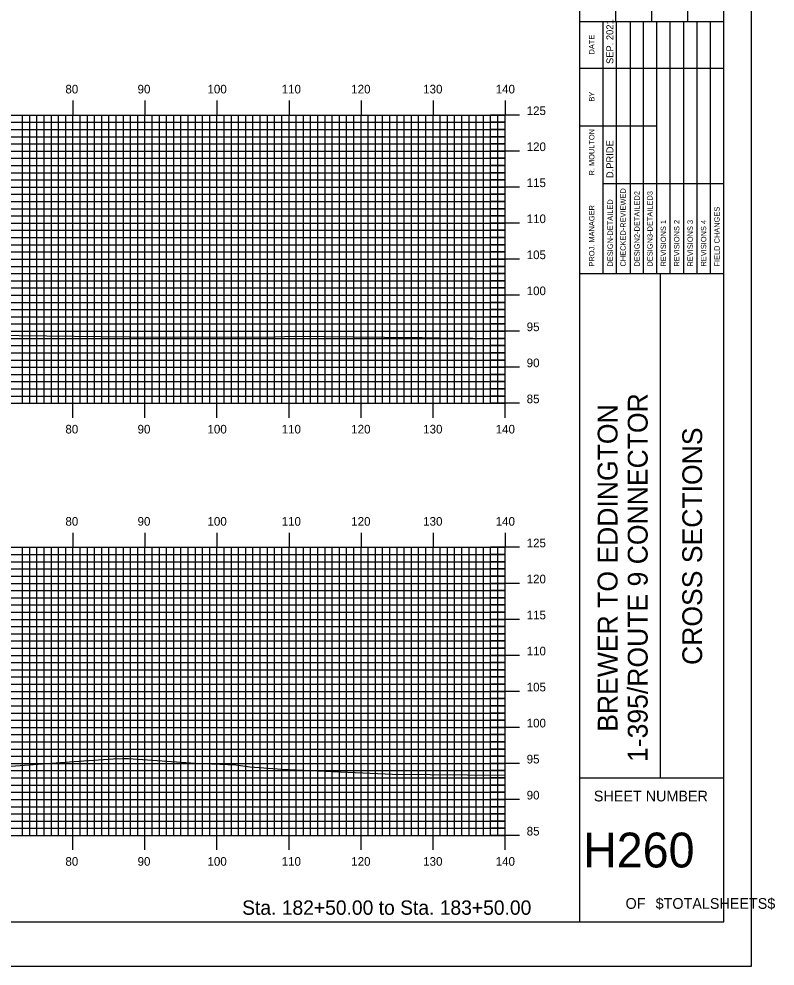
# Model space of a CAD drawing. Extents: x 1786582 to 1786926, y 442591 to 442811.
# Drawn here: x 1786820.6 to 1786925.6, y 442590.5 to 442722 of the extents above; entities that cross this region are included whole.
import ezdxf

# ---------------------------------------------------------------- set-up
doc = ezdxf.new("R2010")
doc.units = 0
for name, color, linetype in [('BORDER', 7, 'Continuous'), ('H_V ANNOTATION', 7, 'Continuous'), ('MAJOR', 7, 'Continuous'), ('MINOR', 7, 'Continuous'), ('PLOT BOUNDARY', 7, 'Continuous'), ('S_Roadway_Centerline', 7, 'Continuous')]:
    doc.layers.add(name, color=color, linetype=linetype)

msp = doc.modelspace()

# ---------------------------------------------------------------- linework, layer by layer
at = {"layer": 'BORDER'}
for p, q in [((1786898.48, 442596.67), (1786898.48, 442806.67)), ((1786903.48, 442721.67), (1786903.48, 442738.97)), ((1786908.48, 442721.67), (1786908.48, 442738.97)), ((1786913.48, 442721.67), (1786913.48, 442738.97)), ((1786898.48, 442721.67), (1786918.48, 442721.67)), ((1786898.48, 442686.67), (1786918.48, 442686.67)), ((1786909.66, 442616.67), (1786909.66, 442686.67)), ((1786898.48, 442616.67), (1786918.48, 442616.67))]:
    msp.add_line(p, q, dxfattribs=at)
msp.add_lwpolyline([(1786598.48, 442596.67), (1786918.48, 442596.67), (1786918.48, 442806.67), (1786598.48, 442806.67)], close=True, dxfattribs=at)
for points in [[(1786901.71, 442715.17), (1786901.71, 442721.67)], [(1786903.57, 442686.68), (1786903.57, 442721.67)], [(1786905.44, 442721.67), (1786905.44, 442686.68)], [(1786907.3, 442686.68), (1786907.3, 442721.67)], [(1786909.16, 442686.68), (1786909.16, 442721.67)], [(1786911.03, 442686.68), (1786911.03, 442721.67)], [(1786912.89, 442686.68), (1786912.89, 442721.67)], [(1786914.75, 442686.68), (1786914.75, 442721.67)], [(1786916.62, 442686.68), (1786916.62, 442721.67)], [(1786901.71, 442686.68), (1786901.71, 442720.26)], [(1786898.48, 442715.17), (1786918.48, 442715.17)], [(1786898.48, 442707.17), (1786901.71, 442707.17)], [(1786901.71, 442707.17), (1786909.16, 442707.17)], [(1786901.71, 442699.17), (1786918.48, 442699.17)]]:
    msp.add_lwpolyline(points, dxfattribs=at)
at = {"layer": 'MAJOR'}
for p, q in [((1786828.08, 442710.67), (1786828.08, 442708.67)), ((1786838.08, 442710.67), (1786838.08, 442708.67)), ((1786848.08, 442710.67), (1786848.08, 442708.67)), ((1786858.08, 442710.67), (1786858.08, 442708.67)), ((1786868.08, 442710.67), (1786868.08, 442708.67)), ((1786878.08, 442710.67), (1786878.08, 442708.67)), ((1786888.08, 442710.67), (1786888.08, 442708.67)), ((1786608.08, 442708.67), (1786888.08, 442708.67)), ((1786608.08, 442708.67), (1786888.08, 442708.67)), ((1786828.08, 442668.67), (1786828.08, 442708.67)), ((1786838.08, 442668.67), (1786838.08, 442708.67)), ((1786848.08, 442668.67), (1786848.08, 442708.67)), ((1786858.08, 442668.67), (1786858.08, 442708.67)), ((1786868.08, 442668.67), (1786868.08, 442708.67)), ((1786878.08, 442668.67), (1786878.08, 442708.67)), ((1786890.08, 442708.67), (1786886.07, 442708.67)), ((1786888.08, 442668.67), (1786888.08, 442708.67)), ((1786888.08, 442668.67), (1786888.08, 442708.67)), ((1786608.08, 442703.67), (1786888.08, 442703.67)), ((1786890.08, 442703.67), (1786886.07, 442703.67)), ((1786608.08, 442698.67), (1786888.08, 442698.67)), ((1786890.08, 442698.67), (1786886.07, 442698.67)), ((1786608.08, 442693.67), (1786888.08, 442693.67)), ((1786890.08, 442693.67), (1786886.07, 442693.67)), ((1786608.08, 442688.67), (1786888.08, 442688.67)), ((1786890.08, 442688.67), (1786886.07, 442688.67)), ((1786608.08, 442683.67), (1786888.08, 442683.67)), ((1786890.08, 442683.67), (1786886.07, 442683.67)), ((1786608.08, 442678.67), (1786888.08, 442678.67)), ((1786890.08, 442678.67), (1786886.07, 442678.67)), ((1786608.08, 442673.67), (1786888.08, 442673.67)), ((1786890.08, 442673.67), (1786886.07, 442673.67)), ((1786608.08, 442668.67), (1786888.08, 442668.67)), ((1786608.08, 442668.67), (1786888.08, 442668.67)), ((1786828.08, 442666.66), (1786828.08, 442668.67)), ((1786838.08, 442666.66), (1786838.08, 442668.67)), ((1786848.08, 442666.66), (1786848.08, 442668.67)), ((1786858.08, 442666.66), (1786858.08, 442668.67)), ((1786868.08, 442666.66), (1786868.08, 442668.67)), ((1786878.08, 442666.66), (1786878.08, 442668.67)), ((1786890.08, 442668.67), (1786886.07, 442668.67)), ((1786888.08, 442666.66), (1786888.08, 442668.67)), ((1786828.08, 442650.67), (1786828.08, 442648.67)), ((1786838.08, 442650.67), (1786838.08, 442648.67)), ((1786848.08, 442650.67), (1786848.08, 442648.67)), ((1786858.08, 442650.67), (1786858.08, 442648.67)), ((1786868.08, 442650.67), (1786868.08, 442648.67)), ((1786878.08, 442650.67), (1786878.08, 442648.67)), ((1786888.08, 442650.67), (1786888.08, 442648.67)), ((1786608.08, 442648.67), (1786888.08, 442648.67)), ((1786608.08, 442648.67), (1786888.08, 442648.67)), ((1786828.08, 442608.67), (1786828.08, 442648.67)), ((1786838.08, 442608.67), (1786838.08, 442648.67)), ((1786848.08, 442608.67), (1786848.08, 442648.67)), ((1786858.08, 442608.67), (1786858.08, 442648.67)), ((1786868.08, 442608.67), (1786868.08, 442648.67)), ((1786878.08, 442608.67), (1786878.08, 442648.67)), ((1786890.08, 442648.67), (1786886.07, 442648.67)), ((1786888.08, 442608.67), (1786888.08, 442648.67)), ((1786888.08, 442608.67), (1786888.08, 442648.67)), ((1786608.08, 442643.67), (1786888.08, 442643.67)), ((1786890.08, 442643.67), (1786886.07, 442643.67)), ((1786608.08, 442638.67), (1786888.08, 442638.67)), ((1786890.08, 442638.67), (1786886.07, 442638.67)), ((1786608.08, 442633.67), (1786888.08, 442633.67)), ((1786890.08, 442633.67), (1786886.07, 442633.67)), ((1786608.08, 442628.67), (1786888.08, 442628.67)), ((1786890.08, 442628.67), (1786886.07, 442628.67)), ((1786608.08, 442623.67), (1786888.08, 442623.67)), ((1786890.08, 442623.67), (1786886.07, 442623.67)), ((1786608.08, 442618.67), (1786888.08, 442618.67)), ((1786890.08, 442618.67), (1786886.07, 442618.67)), ((1786608.08, 442613.67), (1786888.08, 442613.67)), ((1786890.08, 442613.67), (1786886.07, 442613.67)), ((1786608.08, 442608.67), (1786888.08, 442608.67)), ((1786608.08, 442608.67), (1786888.08, 442608.67)), ((1786828.08, 442606.66), (1786828.08, 442608.67)), ((1786838.08, 442606.66), (1786838.08, 442608.67)), ((1786848.08, 442606.66), (1786848.08, 442608.67)), ((1786858.08, 442606.66), (1786858.08, 442608.67)), ((1786868.08, 442606.66), (1786868.08, 442608.67)), ((1786878.08, 442606.66), (1786878.08, 442608.67)), ((1786890.08, 442608.67), (1786886.07, 442608.67)), ((1786888.08, 442606.66), (1786888.08, 442608.67))]:
    msp.add_line(p, q, dxfattribs=at)
at = {"layer": 'MINOR'}
for p, q in [((1786821.08, 442668.67), (1786821.08, 442708.67)), ((1786822.08, 442668.67), (1786822.08, 442708.67)), ((1786823.08, 442668.67), (1786823.08, 442708.67)), ((1786824.08, 442668.67), (1786824.08, 442708.67)), ((1786825.08, 442668.67), (1786825.08, 442708.67)), ((1786826.08, 442668.67), (1786826.08, 442708.67)), ((1786827.08, 442668.67), (1786827.08, 442708.67)), ((1786829.08, 442668.67), (1786829.08, 442708.67)), ((1786830.08, 442668.67), (1786830.08, 442708.67)), ((1786831.08, 442668.67), (1786831.08, 442708.67)), ((1786832.08, 442668.67), (1786832.08, 442708.67)), ((1786833.08, 442668.67), (1786833.08, 442708.67)), ((1786834.08, 442668.67), (1786834.08, 442708.67)), ((1786835.08, 442668.67), (1786835.08, 442708.67)), ((1786836.08, 442668.67), (1786836.08, 442708.67)), ((1786837.08, 442668.67), (1786837.08, 442708.67)), ((1786839.08, 442668.67), (1786839.08, 442708.67)), ((1786840.08, 442668.67), (1786840.08, 442708.67)), ((1786841.08, 442668.67), (1786841.08, 442708.67)), ((1786842.08, 442668.67), (1786842.08, 442708.67)), ((1786843.08, 442668.67), (1786843.08, 442708.67)), ((1786844.08, 442668.67), (1786844.08, 442708.67)), ((1786845.08, 442668.67), (1786845.08, 442708.67)), ((1786846.08, 442668.67), (1786846.08, 442708.67)), ((1786847.08, 442668.67), (1786847.08, 442708.67)), ((1786849.08, 442668.67), (1786849.08, 442708.67)), ((1786850.08, 442668.67), (1786850.08, 442708.67)), ((1786851.08, 442668.67), (1786851.08, 442708.67)), ((1786852.08, 442668.67), (1786852.08, 442708.67)), ((1786853.08, 442668.67), (1786853.08, 442708.67)), ((1786854.08, 442668.67), (1786854.08, 442708.67)), ((1786855.08, 442668.67), (1786855.08, 442708.67)), ((1786856.08, 442668.67), (1786856.08, 442708.67)), ((1786857.08, 442668.67), (1786857.08, 442708.67)), ((1786859.08, 442668.67), (1786859.08, 442708.67)), ((1786860.08, 442668.67), (1786860.08, 442708.67)), ((1786861.08, 442668.67), (1786861.08, 442708.67)), ((1786862.08, 442668.67), (1786862.08, 442708.67)), ((1786863.08, 442668.67), (1786863.08, 442708.67)), ((1786864.08, 442668.67), (1786864.08, 442708.67)), ((1786865.08, 442668.67), (1786865.08, 442708.67)), ((1786866.08, 442668.67), (1786866.08, 442708.67)), ((1786867.08, 442668.67), (1786867.08, 442708.67)), ((1786869.08, 442668.67), (1786869.08, 442708.67)), ((1786870.08, 442668.67), (1786870.08, 442708.67)), ((1786871.08, 442668.67), (1786871.08, 442708.67)), ((1786872.08, 442668.67), (1786872.08, 442708.67)), ((1786873.08, 442668.67), (1786873.08, 442708.67)), ((1786874.08, 442668.67), (1786874.08, 442708.67)), ((1786875.08, 442668.67), (1786875.08, 442708.67)), ((1786876.08, 442668.67), (1786876.08, 442708.67)), ((1786877.08, 442668.67), (1786877.08, 442708.67)), ((1786879.08, 442668.67), (1786879.08, 442708.67)), ((1786880.08, 442668.67), (1786880.08, 442708.67)), ((1786881.08, 442668.67), (1786881.08, 442708.67)), ((1786882.08, 442668.67), (1786882.08, 442708.67)), ((1786883.08, 442668.67), (1786883.08, 442708.67)), ((1786884.08, 442668.67), (1786884.08, 442708.67)), ((1786885.08, 442668.67), (1786885.08, 442708.67)), ((1786886.08, 442668.67), (1786886.08, 442708.67)), ((1786887.08, 442668.67), (1786887.08, 442708.67)), ((1786608.08, 442707.67), (1786888.08, 442707.67)), ((1786888.08, 442707.67), (1786886.07, 442707.67)), ((1786608.08, 442706.67), (1786888.08, 442706.67)), ((1786608.08, 442705.67), (1786888.08, 442705.67)), ((1786888.08, 442706.67), (1786886.07, 442706.67)), ((1786888.08, 442705.67), (1786886.07, 442705.67)), ((1786608.08, 442704.67), (1786888.08, 442704.67)), ((1786888.08, 442704.67), (1786886.07, 442704.67)), ((1786608.08, 442702.67), (1786888.08, 442702.67)), ((1786608.08, 442701.67), (1786888.08, 442701.67)), ((1786888.08, 442702.67), (1786886.07, 442702.67)), ((1786888.08, 442701.67), (1786886.07, 442701.67)), ((1786608.08, 442700.67), (1786888.08, 442700.67)), ((1786888.08, 442700.67), (1786886.07, 442700.67)), ((1786608.08, 442699.67), (1786888.08, 442699.67)), ((1786888.08, 442699.67), (1786886.07, 442699.67)), ((1786608.08, 442697.67), (1786888.08, 442697.67)), ((1786888.08, 442697.67), (1786886.07, 442697.67)), ((1786608.08, 442696.67), (1786888.08, 442696.67)), ((1786888.08, 442696.67), (1786886.07, 442696.67)), ((1786608.08, 442695.67), (1786888.08, 442695.67)), ((1786888.08, 442695.67), (1786886.07, 442695.67)), ((1786608.08, 442694.67), (1786888.08, 442694.67)), ((1786888.08, 442694.67), (1786886.07, 442694.67)), ((1786608.08, 442692.67), (1786888.08, 442692.67)), ((1786888.08, 442692.67), (1786886.07, 442692.67)), ((1786608.08, 442691.67), (1786888.08, 442691.67)), ((1786888.08, 442691.67), (1786886.07, 442691.67)), ((1786608.08, 442690.67), (1786888.08, 442690.67)), ((1786888.08, 442690.67), (1786886.07, 442690.67)), ((1786608.08, 442689.67), (1786888.08, 442689.67)), ((1786888.08, 442689.67), (1786886.07, 442689.67)), ((1786608.08, 442687.67), (1786888.08, 442687.67)), ((1786888.08, 442687.67), (1786886.07, 442687.67)), ((1786608.08, 442686.67), (1786888.08, 442686.67)), ((1786888.08, 442686.67), (1786886.07, 442686.67)), ((1786608.08, 442685.67), (1786888.08, 442685.67)), ((1786608.08, 442684.67), (1786888.08, 442684.67)), ((1786888.08, 442685.67), (1786886.07, 442685.67)), ((1786888.08, 442684.67), (1786886.07, 442684.67)), ((1786608.08, 442682.67), (1786888.08, 442682.67)), ((1786888.08, 442682.67), (1786886.07, 442682.67)), ((1786608.08, 442681.67), (1786888.08, 442681.67)), ((1786608.08, 442680.67), (1786888.08, 442680.67)), ((1786888.08, 442681.67), (1786886.07, 442681.67)), ((1786888.08, 442680.67), (1786886.07, 442680.67)), ((1786608.08, 442679.67), (1786888.08, 442679.67)), ((1786888.08, 442679.67), (1786886.07, 442679.67)), ((1786608.08, 442677.67), (1786888.08, 442677.67)), ((1786608.08, 442676.67), (1786888.08, 442676.67)), ((1786888.08, 442677.67), (1786886.07, 442677.67)), ((1786888.08, 442676.67), (1786886.07, 442676.67)), ((1786608.08, 442675.67), (1786888.08, 442675.67)), ((1786888.08, 442675.67), (1786886.07, 442675.67)), ((1786608.08, 442674.67), (1786888.08, 442674.67)), ((1786888.08, 442674.67), (1786886.07, 442674.67)), ((1786608.08, 442672.67), (1786888.08, 442672.67)), ((1786888.08, 442672.67), (1786886.07, 442672.67)), ((1786608.08, 442671.67), (1786888.08, 442671.67)), ((1786888.08, 442671.67), (1786886.07, 442671.67)), ((1786608.08, 442670.67), (1786888.08, 442670.67)), ((1786888.08, 442670.67), (1786886.07, 442670.67)), ((1786608.08, 442669.67), (1786888.08, 442669.67)), ((1786888.08, 442669.67), (1786886.07, 442669.67)), ((1786608.08, 442647.67), (1786888.08, 442647.67)), ((1786821.08, 442608.67), (1786821.08, 442648.67)), ((1786822.08, 442608.67), (1786822.08, 442648.67)), ((1786823.08, 442608.67), (1786823.08, 442648.67)), ((1786824.08, 442608.67), (1786824.08, 442648.67)), ((1786825.08, 442608.67), (1786825.08, 442648.67)), ((1786826.08, 442608.67), (1786826.08, 442648.67)), ((1786827.08, 442608.67), (1786827.08, 442648.67)), ((1786829.08, 442608.67), (1786829.08, 442648.67)), ((1786830.08, 442608.67), (1786830.08, 442648.67)), ((1786831.08, 442608.67), (1786831.08, 442648.67)), ((1786832.08, 442608.67), (1786832.08, 442648.67)), ((1786833.08, 442608.67), (1786833.08, 442648.67)), ((1786834.08, 442608.67), (1786834.08, 442648.67)), ((1786835.08, 442608.67), (1786835.08, 442648.67)), ((1786836.08, 442608.67), (1786836.08, 442648.67)), ((1786837.08, 442608.67), (1786837.08, 442648.67)), ((1786839.08, 442608.67), (1786839.08, 442648.67)), ((1786840.08, 442608.67), (1786840.08, 442648.67)), ((1786841.08, 442608.67), (1786841.08, 442648.67)), ((1786842.08, 442608.67), (1786842.08, 442648.67)), ((1786843.08, 442608.67), (1786843.08, 442648.67)), ((1786844.08, 442608.67), (1786844.08, 442648.67)), ((1786845.08, 442608.67), (1786845.08, 442648.67)), ((1786846.08, 442608.67), (1786846.08, 442648.67)), ((1786847.08, 442608.67), (1786847.08, 442648.67)), ((1786849.08, 442608.67), (1786849.08, 442648.67)), ((1786850.08, 442608.67), (1786850.08, 442648.67)), ((1786851.08, 442608.67), (1786851.08, 442648.67)), ((1786852.08, 442608.67), (1786852.08, 442648.67)), ((1786853.08, 442608.67), (1786853.08, 442648.67)), ((1786854.08, 442608.67), (1786854.08, 442648.67)), ((1786855.08, 442608.67), (1786855.08, 442648.67)), ((1786856.08, 442608.67), (1786856.08, 442648.67)), ((1786857.08, 442608.67), (1786857.08, 442648.67)), ((1786859.08, 442608.67), (1786859.08, 442648.67)), ((1786860.08, 442608.67), (1786860.08, 442648.67)), ((1786861.08, 442608.67), (1786861.08, 442648.67)), ((1786862.08, 442608.67), (1786862.08, 442648.67)), ((1786863.08, 442608.67), (1786863.08, 442648.67)), ((1786864.08, 442608.67), (1786864.08, 442648.67)), ((1786865.08, 442608.67), (1786865.08, 442648.67)), ((1786866.08, 442608.67), (1786866.08, 442648.67)), ((1786867.08, 442608.67), (1786867.08, 442648.67)), ((1786869.08, 442608.67), (1786869.08, 442648.67)), ((1786870.08, 442608.67), (1786870.08, 442648.67)), ((1786871.08, 442608.67), (1786871.08, 442648.67)), ((1786872.08, 442608.67), (1786872.08, 442648.67)), ((1786873.08, 442608.67), (1786873.08, 442648.67)), ((1786874.08, 442608.67), (1786874.08, 442648.67)), ((1786875.08, 442608.67), (1786875.08, 442648.67)), ((1786876.08, 442608.67), (1786876.08, 442648.67)), ((1786877.08, 442608.67), (1786877.08, 442648.67)), ((1786879.08, 442608.67), (1786879.08, 442648.67)), ((1786880.08, 442608.67), (1786880.08, 442648.67)), ((1786881.08, 442608.67), (1786881.08, 442648.67)), ((1786882.08, 442608.67), (1786882.08, 442648.67)), ((1786883.08, 442608.67), (1786883.08, 442648.67)), ((1786884.08, 442608.67), (1786884.08, 442648.67)), ((1786885.08, 442608.67), (1786885.08, 442648.67)), ((1786888.08, 442647.67), (1786886.07, 442647.67)), ((1786886.08, 442608.67), (1786886.08, 442648.67)), ((1786887.08, 442608.67), (1786887.08, 442648.67)), ((1786608.08, 442646.67), (1786888.08, 442646.67)), ((1786888.08, 442646.67), (1786886.07, 442646.67)), ((1786608.08, 442645.67), (1786888.08, 442645.67)), ((1786888.08, 442645.67), (1786886.07, 442645.67)), ((1786608.08, 442644.67), (1786888.08, 442644.67)), ((1786888.08, 442644.67), (1786886.07, 442644.67)), ((1786608.08, 442642.67), (1786888.08, 442642.67)), ((1786888.08, 442642.67), (1786886.07, 442642.67)), ((1786608.08, 442641.67), (1786888.08, 442641.67)), ((1786888.08, 442641.67), (1786886.07, 442641.67)), ((1786608.08, 442640.67), (1786888.08, 442640.67)), ((1786888.08, 442640.67), (1786886.07, 442640.67)), ((1786608.08, 442639.67), (1786888.08, 442639.67)), ((1786888.08, 442639.67), (1786886.07, 442639.67)), ((1786608.08, 442637.67), (1786888.08, 442637.67)), ((1786888.08, 442637.67), (1786886.07, 442637.67)), ((1786608.08, 442636.67), (1786888.08, 442636.67)), ((1786888.08, 442636.67), (1786886.07, 442636.67)), ((1786608.08, 442635.67), (1786888.08, 442635.67)), ((1786608.08, 442634.67), (1786888.08, 442634.67)), ((1786888.08, 442635.67), (1786886.07, 442635.67)), ((1786888.08, 442634.67), (1786886.07, 442634.67)), ((1786608.08, 442632.67), (1786888.08, 442632.67)), ((1786888.08, 442632.67), (1786886.07, 442632.67)), ((1786608.08, 442631.67), (1786888.08, 442631.67)), ((1786608.08, 442630.67), (1786888.08, 442630.67)), ((1786888.08, 442631.67), (1786886.07, 442631.67)), ((1786888.08, 442630.67), (1786886.07, 442630.67)), ((1786608.08, 442629.67), (1786888.08, 442629.67)), ((1786888.08, 442629.67), (1786886.07, 442629.67)), ((1786608.08, 442627.67), (1786888.08, 442627.67)), ((1786608.08, 442626.67), (1786888.08, 442626.67)), ((1786888.08, 442627.67), (1786886.07, 442627.67)), ((1786888.08, 442626.67), (1786886.07, 442626.67)), ((1786608.08, 442625.67), (1786888.08, 442625.67)), ((1786888.08, 442625.67), (1786886.07, 442625.67)), ((1786608.08, 442624.67), (1786888.08, 442624.67)), ((1786888.08, 442624.67), (1786886.07, 442624.67)), ((1786608.08, 442622.67), (1786888.08, 442622.67)), ((1786888.08, 442622.67), (1786886.07, 442622.67)), ((1786608.08, 442621.67), (1786888.08, 442621.67)), ((1786888.08, 442621.67), (1786886.07, 442621.67)), ((1786608.08, 442620.67), (1786888.08, 442620.67)), ((1786888.08, 442620.67), (1786886.07, 442620.67)), ((1786608.08, 442619.67), (1786888.08, 442619.67)), ((1786888.08, 442619.67), (1786886.07, 442619.67)), ((1786608.08, 442617.67), (1786888.08, 442617.67)), ((1786888.08, 442617.67), (1786886.07, 442617.67)), ((1786608.08, 442616.67), (1786888.08, 442616.67)), ((1786888.08, 442616.67), (1786886.07, 442616.67)), ((1786608.08, 442615.67), (1786888.08, 442615.67)), ((1786888.08, 442615.67), (1786886.07, 442615.67)), ((1786608.08, 442614.67), (1786888.08, 442614.67)), ((1786888.08, 442614.67), (1786886.07, 442614.67)), ((1786608.08, 442612.67), (1786888.08, 442612.67)), ((1786888.08, 442612.67), (1786886.07, 442612.67)), ((1786608.08, 442611.67), (1786888.08, 442611.67)), ((1786888.08, 442611.67), (1786886.07, 442611.67)), ((1786608.08, 442610.67), (1786888.08, 442610.67)), ((1786608.08, 442609.67), (1786888.08, 442609.67)), ((1786888.08, 442610.67), (1786886.07, 442610.67)), ((1786888.08, 442609.67), (1786886.07, 442609.67))]:
    msp.add_line(p, q, dxfattribs=at)
at = {"layer": 'PLOT BOUNDARY'}
msp.add_lwpolyline([(1786582.29, 442590.55), (1786922.29, 442590.55), (1786922.29, 442810.55), (1786582.29, 442810.55)], close=True, dxfattribs=at)
at = {"layer": 'S_Roadway_Centerline'}
for points in [[(1786714.12, 442679.12), (1786728.66, 442678.82), (1786734.64, 442678.69), (1786736.71, 442678.65), (1786754.79, 442678.45), (1786758.83, 442678.46), (1786764.8, 442678.47), (1786770.83, 442678.42), (1786774.97, 442678.43), (1786792.58, 442678.25), (1786795.62, 442678.21), (1786805.81, 442678.26), (1786815.58, 442678.17), (1786817.67, 442678.15), (1786820.6, 442678.09), (1786835.94, 442677.89), (1786848.4, 442677.84), (1786856.15, 442677.87), (1786858.78, 442677.98), (1786875.5, 442677.8), (1786876.15, 442677.79), (1786876.58, 442677.79), (1786879.11, 442677.76), (1786888.08, 442677.67)], [(1786811.9, 442617.72), (1786828.25, 442618.95), (1786833.66, 442619.31), (1786834.94, 442619.36), (1786835.78, 442619.35), (1786845.09, 442618.7), (1786850.7, 442618.5), (1786852.63, 442618.19), (1786857.11, 442617.88), (1786863.13, 442617.6), (1786872.46, 442617.16), (1786888.08, 442617.06)]]:
    msp.add_lwpolyline(points, dxfattribs=at)

# ---------------------------------------------------------------- texts
at = {"layer": 'BORDER'}
for s, height, p in [('SEP. 2021', 0.969, (1786903.12, 442715.76)), ('DATE', 0.743, (1786900.49, 442717.08)), ('BY', 0.743, (1786900.49, 442710.54)), ('R. MOULTON', 0.745, (1786900.49, 442700.28)), ('D.PRIDE', 0.969, (1786903.12, 442699.92)), ('CHECKED-REVIEWED', 0.7455, (1786904.84, 442687.65)), ('DESIGN2-DETAILED2', 0.7455, (1786906.78, 442687.65)), ('DESIGN3-DETAILED3', 0.7455, (1786908.57, 442687.65)), ('DESIGN-DETAILED', 0.7455, (1786903.05, 442687.65)), ('PROJ. MANAGER', 0.7455, (1786900.49, 442687.65)), ('FIELD CHANGES', 0.7455, (1786917.88, 442687.65)), ('REVISIONS 1', 0.7455, (1786910.43, 442687.65)), ('REVISIONS 2', 0.7455, (1786912.29, 442687.65)), ('REVISIONS 3', 0.7455, (1786914.16, 442687.65)), ('REVISIONS 4', 0.7455, (1786916.02, 442687.65)), ('1-395/ROUTE 9 CONNECTOR', 2.7557, (1786907.88, 442618.87)), ('BREWER TO EDDINGTON', 2.7557, (1786903.7, 442623.07)), ('CROSS SECTIONS', 2.7557, (1786915.45, 442632.34))]:
    msp.add_text(s, height=height, rotation=90, dxfattribs=at).set_placement(p)
for s, height, p in [('SHEET NUMBER', 1.4905, (1786900.41, 442613.4)), ('H260', 4.839, (1786898.92, 442604.23)), ('OF', 1.491, (1786904.81, 442598.49)), ('$TOTALSHEETS$', 1.4905, (1786908.99, 442598.49))]:
    msp.add_text(s, height=height, dxfattribs=at).set_placement(p)
at = {"layer": 'H_V ANNOTATION'}
for s, height, p in [('80', 1.2, (1786827.03, 442711.67)), ('90', 1.2, (1786837.05, 442711.67)), ('100', 1.2, (1786846.76, 442711.67)), ('110', 1.2, (1786857.06, 442711.67)), ('120', 1.2, (1786866.72, 442711.67)), ('130', 1.2, (1786876.71, 442711.67)), ('140', 1.2, (1786886.78, 442711.67)), ('125', 1.2, (1786891.08, 442708.67)), ('120', 1.2, (1786891.08, 442703.67)), ('115', 1.2, (1786891.08, 442698.67)), ('110', 1.2, (1786891.08, 442693.67)), ('105', 1.2, (1786891.08, 442688.67)), ('100', 1.2, (1786891.08, 442683.67)), ('95', 1.2, (1786891.08, 442678.67)), ('90', 1.2, (1786891.08, 442673.67)), ('85', 1.2, (1786891.08, 442668.67)), ('80', 1.2, (1786827.03, 442664.47)), ('90', 1.2, (1786837.05, 442664.47)), ('100', 1.2, (1786846.76, 442664.47)), ('110', 1.2, (1786857.06, 442664.47)), ('120', 1.2, (1786866.72, 442664.47)), ('130', 1.2, (1786876.71, 442664.47)), ('140', 1.2, (1786886.78, 442664.47)), ('80', 1.2, (1786827.03, 442651.67)), ('90', 1.2, (1786837.05, 442651.67)), ('100', 1.2, (1786846.76, 442651.67)), ('110', 1.2, (1786857.06, 442651.67)), ('120', 1.2, (1786866.72, 442651.67)), ('130', 1.2, (1786876.71, 442651.67)), ('140', 1.2, (1786886.78, 442651.67)), ('125', 1.2, (1786891.08, 442648.67)), ('120', 1.2, (1786891.08, 442643.67)), ('115', 1.2, (1786891.08, 442638.67)), ('110', 1.2, (1786891.08, 442633.67)), ('105', 1.2, (1786891.08, 442628.67)), ('100', 1.2, (1786891.08, 442623.67)), ('95', 1.2, (1786891.08, 442618.67)), ('90', 1.2, (1786891.08, 442613.67)), ('85', 1.2, (1786891.08, 442608.67)), ('80', 1.2, (1786827.03, 442604.47)), ('90', 1.2, (1786837.05, 442604.47)), ('100', 1.2, (1786846.76, 442604.47)), ('110', 1.2, (1786857.06, 442604.47)), ('120', 1.2, (1786866.72, 442604.47)), ('130', 1.2, (1786876.71, 442604.47)), ('140', 1.2, (1786886.78, 442604.47)), ('Sta. 182+50.00 to Sta. 183+50.00', 2.0004, (1786851.57, 442597.66))]:
    msp.add_text(s, height=height, dxfattribs=at).set_placement(p)

doc.saveas('drawing.dxf')
